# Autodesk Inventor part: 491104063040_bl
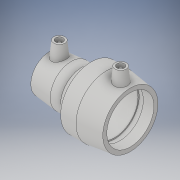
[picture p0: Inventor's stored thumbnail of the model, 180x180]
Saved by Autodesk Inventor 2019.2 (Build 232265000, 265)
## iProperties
Created: 2017-06
Part Number: 491104063040_bl
Material: Generic
Description: PLASSON REDUCING COUPLER 63-40
Document SubType Name: Modeling
Designer: KIM
Mass: 54.8237 g
Surface Area: 155.252 cm^2
Volume: 54.8237 cm^3
Density: 1 g/cm^3
Appearance: Default
Author: KIM
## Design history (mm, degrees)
derived "491104 (Type 3).ipt"
feature "Solid1::491104 (Type 3).ipt" dims "ScaleForDerivedMember" = 10
tag "TaggingFeature1"
body "Solid1"
other parameters: "L_" = 108 [user parameter], "L_2" = 48 [user parameter], "D_1" = 56 [user parameter], "A_1" = 45 [user parameter], "d_2" = 12 [user parameter], "L_1" = 53 [user parameter], "d_" = 63 [user parameter], "A_" = 56 [user parameter], "D_" = 82 [user parameter], "d0" = 108 [user parameter], "d2" = 56 [user parameter], "d3" = 48 [user parameter], "d4" = 28.8 [user parameter], "d5" = 50.4 [user parameter], "d8" = 168 deg [user parameter], "d10" = 19.2 [user parameter], "d11" = 6.4 [user parameter], "d13" = 108 [user parameter], "d14" = 17.6296 [user parameter], "d15" = 48 [user parameter], "d19" = 2.4 [user parameter], "d20" = 168 deg [user parameter], "d22" = 108.92847 [user parameter], "d25" = 135 deg [user parameter], "d29" = 45 [user parameter], "d30" = 15 [user parameter], "d31" = 41.04 [user parameter], "d34" = 6 deg [user parameter], "d35" = 15 [user parameter], "d38" = 23 [user parameter], "d39" = 5 deg [user parameter], "d41" = 4 [user parameter], "d42" = 14 [user parameter], "d43" = 0 [user parameter], "d45" = 4 [user parameter], "d46" = 14 [user parameter], "d47" = 0 [user parameter], "d48" = 56 [user parameter], "d49" = 63 [user parameter], "d50" = 82 [user parameter], "d52" = 36 [user parameter], "d53" = 21.2 [user parameter], "d54" = 7.06667 [user parameter], "d55" = 168 deg [user parameter], "d56" = 31.8 [user parameter], "d57" = 53 [user parameter], "d58" = 73.8 [user parameter], "d59" = 2.4 [user parameter], "d60" = 135 deg [user parameter], "d61" = 56 [user parameter], "d62" = 15 [user parameter], "d64" = 4 [user parameter], "d66" = 5 deg [user parameter], "d67" = 14 [user parameter], "d68" = 0 [user parameter], "d69" = 41.04 [user parameter], "d70" = 56 [user parameter], "d71" = 82 [user parameter], "d73" = 77.08 [user parameter], "d76" = 2.4 [user parameter], "d77" = 168 deg [user parameter], "d78" = 63 [user parameter], "d79" = 2.4 [user parameter], "d80" = 53 [user parameter], "d81" = 36 [user parameter], "d82" = 52.64 [user parameter], "d83" = 120 deg [user parameter], "d88" = 15 [user parameter], "d89" = 21.35 [user parameter], "d90" = 5 deg [user parameter], "d92" = 4 [user parameter], "d93" = 14 [user parameter], "d94" = 0 [user parameter], "d95" = 3 [user parameter], "d96" = 0 [user parameter], "d97" = 3 [user parameter], "d98" = 0 [user parameter], "d99" = 13.92 [user parameter], "d100" = 3.48 [user parameter], "d101" = 51.0608 [user parameter], "d102" = 20 deg [user parameter], "d103" = 15.37 [user parameter], "d104" = 3.8425 [user parameter], "d105" = 74.7676 [user parameter], "d106" = 3.60705 [user parameter], "d107" = 3 [user parameter], "d108" = 0 [user parameter], "d109" = 3 [user parameter], "d110" = 0 [user parameter]
